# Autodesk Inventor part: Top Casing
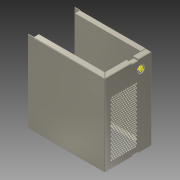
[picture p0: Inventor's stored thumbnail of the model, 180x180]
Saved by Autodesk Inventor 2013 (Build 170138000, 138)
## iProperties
Created: 2005-12
Material: Allgemein
Document SubType Name: Sheet Metal
Mass: 57.0639 g
Surface Area: 1197.17 cm^2
Volume: 57.0639 cm^3
Density: 1 g/cm^3
Flat Pattern Width: 16.7355 cm
Flat Pattern Length: 36.7355 cm
Flat Pattern Area: 614.789 cm^2
Sheet Metal Rule: 1.0 mm
Sheet Metal Width: 167.355 mm
Sheet Metal Length: 367.355 mm
Sheet Metal Area: 61478.899 mm^2
Author: Autodesk, Inc.
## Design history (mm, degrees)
node "Face1"
  sketch "Sketch2"
    geometry: L1 (0, 150)-(0, 0); L2 (-85, 150)-(0, 150); L3 (-85, 0)-(-85, 150); L4 (0, 0)-(-85, 0)
    constraints: 8 end point
node "Flange3"
node "Flange4"
node "Flange5"
node "Flange6"
node "Flange7"
node "Flange8"
node "Flange9"
node "Flange10"
feature "Corner1" dims "d85" = 4 (= CornerReliefSize), "d86" = 0.5 (= BendRadius), "d87" = 1 (= Thickness), "d88" = 0, "Thickness" = 1
feature "Corner2" dims "d89" = 4 (= CornerReliefSize), "d90" = 0.5 (= BendRadius), "d91" = 1 (= Thickness), "d92" = 0, "Thickness" = 1
feature "Corner3" dims "d93" = 4 (= CornerReliefSize), "d94" = 0.5 (= BendRadius), "d95" = 1 (= Thickness), "d96" = 0, "Thickness" = 1
feature "Corner4" dims "d97" = 4 (= CornerReliefSize), "d98" = 0.5 (= BendRadius), "d99" = 1 (= Thickness), "d100" = 0, "Thickness" = 1
cut "Cut1" dims "d104" = 1 (= Thickness), "d105" = 0
node "Flange11"
workplane "Work Plane1"
mirror "Mirror1"
cut "Cut3" dims "d143" = 1 (derived), "d144" = 0
feature "iFeature2:1" dims "d156" = 4
sketch "Sketch18"
  geometry: L1 (60.5, 148)-(60.5, 145.978) reference; L2 (59.5, 145.978)-(49.5, 145.978) reference; L3 (48.5, 145.978)-(48.5, 148) reference; L4 (0, 148)-(48.5, 148) reference; L5 (0, 148)-(0, 0) reference; L6 (48.5, 0)-(0, 0) reference; L7 (48.5, 0)-(48.5, 2.022) reference; L8 (49.5, 2.022)-(59.5, 2.022) reference; L9 (60.5, 2.022)-(60.5, 0) reference; L10 (84, 0)-(60.5, 0) reference; L11 (84, 0)-(84, 148) reference; L12 (60.5, 148)-(84, 148) reference; C1 r 7.5 at (65.5, 131.5) reference; A1 r 0.5 centre (60, 145.978) between (59.5, 145.978) and (60.5, 145.978) reference; A2 r 0.5 centre (49, 145.978) between (48.5, 145.978) and (49.5, 145.978) reference; A3 r 0.5 centre (49, 2.022) between (49.5, 2.022) and (48.5, 2.022) reference; A4 r 0.5 centre (60, 2.022) between (60.5, 2.022) and (59.5, 2.022) reference; 4 further points
workpoint "Work Point1"
workpoint "Work Point3"
workpoint "Work Point4"
workplane "Work Plane2"
workpoint "Work Point5"
workpoint "Work Point7"
workpoint "Work Point8"
workpoint "Work Point9"
workpoint "Work Point10"
body "Solid1"
sketch "Sketch19"
  geometry: 4 further points
face "Plate1" dims "Thickness" = 1
sketch "Sketch5"
  geometry: L1 through (0, 75) direction (5.8e-32, 1); L2 (0, 150)-(142, 150); L3 (142, 150)-(142, 0); L4 through (71, 0) direction (-1, 1.14e-31)
  constraints: 6 end point, 1 horizontal, 1 perpendicular, 1 vertical
face "Plate4" dims "d19" = 2 (= MinimumRemnant), "d21" = 142 (= d16), "d22" = 90 deg, "d23" = 0.5 (= BendRadius), "SeamGap" = 0.01, "Thickness" = 1
bend "Bend3" dims "d17" = 1 (= BendReliefWidth), "d18" = 0.5 (= BendReliefDepth), "d19" = 2 (= MinimumRemnant), "d20" = 0.5 (= BendRadius), "d21" = 142 (= d16), "d22" = 90 deg, "d23" = 0.5 (= BendRadius), "SeamGap" = 0.01, "Thickness" = 1
sketch "Sketch6"
  geometry: L1 through (0, -75) direction (0, -1); L2 (0, -150)-(-142, -150); L3 (-142, -150)-(-142, 0); L4 through (-71, 0) direction (1, 0)
  constraints: 6 end point, 1 horizontal, 1 perpendicular, 1 vertical
face "Plate5" dims "d26" = 2 (= MinimumRemnant), "d28" = 142 (= d16), "d29" = 90 deg, "d30" = 0.5 (= BendRadius), "SeamGap" = 0.01, "Thickness" = 1
bend "Bend4" dims "d24" = 1 (= BendReliefWidth), "d25" = 0.5 (= BendReliefDepth), "d26" = 2 (= MinimumRemnant), "d27" = 0.5 (= BendRadius), "d28" = 142 (= d16), "d29" = 90 deg, "d30" = 0.5 (= BendRadius), "SeamGap" = 0.01, "Thickness" = 1
sketch "Sketch7"
  geometry: L1 (10, 0)-(128.5, 0); L2 (128.5, 0)-(128.5, -10); L3 (128.5, -10)-(10, -10); L4 (10, -10)-(10, 0)
  constraints: 8 end point
face "Plate6" dims "d31" = 10, "d32" = 12, "d35" = 2 (= MinimumRemnant), "d37" = 10, "d38" = 90 deg, "d39" = 0.5 (= BendRadius), "SeamGap" = 0.01, "Thickness" = 1
bend "Bend5" dims "d33" = 1 (= BendReliefWidth), "d34" = 0.5 (= BendReliefDepth), "d35" = 2 (= MinimumRemnant), "d36" = 0.5 (= BendRadius), "d37" = 10, "d38" = 90 deg, "d39" = 0.5 (= BendRadius), "SeamGap" = 0.01, "Thickness" = 1
sketch "Sketch8"
  geometry: L1 (12, 0)-(130.5, 0); L2 (130.5, 0)-(130.5, -10); L3 (130.5, -10)-(12, -10); L4 (12, -10)-(12, 0)
  constraints: 8 end point
face "Plate7" dims "d40" = 12, "d41" = 10, "d44" = 2 (= MinimumRemnant), "d46" = 10, "d47" = 90 deg, "d48" = 0.5 (= BendRadius), "SeamGap" = 0.01, "Thickness" = 1
bend "Bend6" dims "d42" = 1 (= BendReliefWidth), "d43" = 0.5 (= BendReliefDepth), "d44" = 2 (= MinimumRemnant), "d45" = 0.5 (= BendRadius), "d46" = 10, "d47" = 90 deg, "d48" = 0.5 (= BendRadius), "SeamGap" = 0.01, "Thickness" = 1
sketch "Sketch9"
  geometry: L1 (0, -12)-(0, -72); L2 (0, -72)-(-10, -72); L3 (-10, -72)-(-10, -12); L4 (-10, -12)-(0, -12)
  constraints: 8 end point
face "Plate8" dims "d49" = 12, "d50" = 12, "d53" = 2 (= MinimumRemnant), "d55" = 10, "d56" = 90 deg, "d57" = 0.5 (= BendRadius), "SeamGap" = 0.01, "Thickness" = 1
bend "Bend7" dims "d51" = 1 (= BendReliefWidth), "d52" = 0.5 (= BendReliefDepth), "d53" = 2 (= MinimumRemnant), "d54" = 0.5 (= BendRadius), "d55" = 10, "d56" = 90 deg, "d57" = 0.5 (= BendRadius), "SeamGap" = 0.01, "Thickness" = 1
sketch "Sketch10"
  geometry: L1 (-12, 0)-(-130.5, 0); L2 (-130.5, 0)-(-130.5, 10); L3 (-130.5, 10)-(-12, 10); L4 (-12, 10)-(-12, 0)
  constraints: 8 end point
face "Plate9" dims "d58" = 12, "d59" = 10, "d62" = 2 (= MinimumRemnant), "d64" = 10, "d65" = 90 deg, "d66" = 0.5 (= BendRadius), "SeamGap" = 0.01, "Thickness" = 1
bend "Bend8" dims "d60" = 1 (= BendReliefWidth), "d61" = 0.5 (= BendReliefDepth), "d62" = 2 (= MinimumRemnant), "d63" = 0.5 (= BendRadius), "d64" = 10, "d65" = 90 deg, "d66" = 0.5 (= BendRadius), "SeamGap" = 0.01, "Thickness" = 1
sketch "Sketch11"
  geometry: L1 (-10, 0)-(-128.5, 0); L2 (-128.5, 0)-(-128.5, 10); L3 (-128.5, 10)-(-10, 10); L4 (-10, 10)-(-10, 0)
  constraints: 8 end point
face "Plate10" dims "d67" = 10, "d68" = 12, "d71" = 2 (= MinimumRemnant), "d73" = 10, "d74" = 90 deg, "d75" = 0.5 (= BendRadius), "SeamGap" = 0.01, "Thickness" = 1
bend "Bend9" dims "d69" = 1 (= BendReliefWidth), "d70" = 0.5 (= BendReliefDepth), "d71" = 2 (= MinimumRemnant), "d72" = 0.5 (= BendRadius), "d73" = 10, "d74" = 90 deg, "d75" = 0.5 (= BendRadius), "SeamGap" = 0.01, "Thickness" = 1
sketch "Sketch12"
  geometry: L1 (0, 12)-(0, 72); L2 (0, 72)-(10, 72); L3 (10, 72)-(10, 12); L4 (10, 12)-(0, 12)
  constraints: 8 end point
face "Plate11" dims "d76" = 12, "d77" = 12, "d80" = 2 (= MinimumRemnant), "d82" = 10, "d83" = 90 deg, "d84" = 0.5 (= BendRadius), "SeamGap" = 0.01, "Thickness" = 1
bend "Bend10" dims "d78" = 1 (= BendReliefWidth), "d79" = 0.5 (= BendReliefDepth), "d80" = 2 (= MinimumRemnant), "d81" = 0.5 (= BendRadius), "d82" = 10, "d83" = 90 deg, "d84" = 0.5 (= BendRadius), "SeamGap" = 0.01, "Thickness" = 1
sketch "Sketch13"
  geometry: L1 (0, 0)-(0, 74.793) reference; L2 (0, 35.5)-(11.2, 35.5); L3 (11.2, 35.5)-(11.2, 23.5); L4 (11.2, 23.5)-(0, 23.5); L5 (0, 23.5)-(0, 35.5); L6 (-1, -1.5)-(-122, -1.5) reference; L7 (0, 74.793)-(8.5, 83.293) reference; L8 (8.5, 0)-(9.678, 0) reference; L9 (9.678, 0)-(9.678, 84) reference; L10 (8.5, 83.293)-(8.5, 0) reference; L11 (0, 0)-(0, 74.793) reference; L12 (8.5, 0)-(0, 0) reference; L13 (9.089, 83.793)-(9.089, 0) reference; L14 (157.678, 84)-(157.678, 0) reference; L15 (157.678, 84)-(9.678, 84) reference; L16 (9.678, 0)-(157.678, 0) reference
  constraints: 8 end point, 2 parallel, 1 horizontal, 1 perpendicular, 1 point on line
  dimensions: "d101" = 25 distance between parallel lines of L6 L4; "d102" = 12 distance of L2.end L3.end; "d106" = 11.2 distance of L2.start L2.end
sketch "Sketch14"
  geometry: L1 (0, -1)-(0, -11); L2 (0, -11)-(-8, -11); L3 (-8, -11)-(-8, -1); L4 (-8, -1)-(0, -1)
  constraints: 8 end point
face "Plate12" dims "d107" = 1 (= BendReliefWidth), "d109" = 2 (= MinimumRemnant), "d111" = 8, "d112" = 90 deg, "d113" = 0.5 (= BendRadius), "Thickness" = 1
bend "Bend11" dims "d107" = 1 (= BendReliefWidth), "d108" = 0.5 (= BendReliefDepth), "d109" = 2 (= MinimumRemnant), "d110" = 0.5 (= BendRadius), "d111" = 8, "d112" = 90 deg, "d113" = 0.5 (= BendRadius), "SeamGap" = 0.01, "Thickness" = 1
sketch "Sketch15"
  geometry: L1 (-1.5, 148)-(-1.5, 0) reference; L2 (0.707, -1.5)-(48.5, -1.5) reference; 366 further points
  constraints: 6 coincident, 1 horizontal, 1 vertical, 360 other
  dimensions: "d116" = 15 distance from line of L2 point (10.5, 13.5); "d117" = 12 distance from line of point (10.5, 13.5) L1; "d146" = 3.43301 vertical distance of point (12.482, 16.933) point (10.5, 13.5); "d147" = 1.98205 horizontal distance of point (12.482, 16.933) point (10.5, 13.5); "d150" = 6.866 distance of point (10.5, 13.5) point (10.5, 20.366); "d153" = 3.964 distance of point (10.5, 13.5) point (14.464, 13.5)
sketch "Sketch17"
  geometry: L1 (84, 149.5)-(60.5, 149.5) reference; L2 (85.5, 0)-(85.5, 148) reference; C1 r 7.5 at (65.5, 131.5)
  constraints: 1 centre point
  dimensions: "d140" = 18 distance from line of C1.centre L1; "d141" = 20 distance from line of C1.centre L2; "d142" = 15 diameter of C1
feature "Definition1" dims "d0" = 1 (derived)
other parameters: "BendRadius" = 0.5, "BendReliefWidth" = 1 (= Thickness), "BendReliefDepth" = 0.5 (= 0.5 x Thickness), "CornerReliefSize" = 4 (= 4 x Thickness), "MinimumRemnant" = 2 (= 2 x Thickness), "TransitionRadius" = 0.5 (= BendRadius), "d16" = 142 [user parameter; used in 2 equation terms], "d1" = 0.5 (= BendRadius), "d145" = -5, "JacobiRadiusSize" = 1 (derived), "d158" = 0, "GapSize" = 1 (derived), "d16" = 142, "BendRadius" = 0.5, "BendReliefDepth" = 0.5, "BendReliefWidth" = 1, "CornerReliefSize" = 4, "JacobiRadiusSize" = 1, "MinimumRemnant" = 2, "Thickness" = 1, "TransitionRadius" = 0.5, "GapSize" = 1
